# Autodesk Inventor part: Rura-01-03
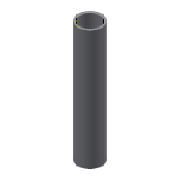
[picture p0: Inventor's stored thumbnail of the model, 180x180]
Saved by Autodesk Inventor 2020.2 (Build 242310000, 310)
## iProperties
Manager: www.cadconsulting.pl
Company: Fabian Stasiak CAD Consulting
IsCustomPart: 0
Created: 2014-07
Part Number: Rura-01-03
Material: Ogólny
Document SubType Name: Modeling
Designer: F.Stasiak
Language: pl-PL
Size Designation: 80
Categories: <MemberInstance><Categories><Category DisplayName="Rury cienko- i grubościenne" InternalName="4347fa0f-2144-441d-94cd-e3e15c92b736" Mnemonic="TUBEANDPIPE"><Cate
Density: 1 g/cm^3
Appearance: Domyślna
Catalog Web Link: www.expertbooks.pl
Author: F.Stasiak
Subject: Zbiór ćwiczeń. Autodesk Inventor 2020. Kurs Professional
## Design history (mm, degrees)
sketch "Szkic1"
  geometry: C1 r 40 at (0, 0); C2 r 45 at (0, 0); 1 further point
  constraints: 2 centre point, 2 coincident
  dimensions: "d0" = 80 diameter of C1 (= ID); "d1" = 90 diameter of C2 (= OD)
extrude "Wyciągnięcie proste1" new body sketch "Szkic1" distance "d2" = 250 (= L); taper "d3" = 0 deg
node "Punkt konstrukcyjny3"
node "Punkt konstrukcyjny4"
node "Oś konstrukcyjna3"
node "Oś konstrukcyjna4"
node "Bryła1"
other parameters: "L" = 250 [user parameter; used in 1 equation term], "ID" = 80 [user parameter; used in 1 equation term], "OD" = 90 [user parameter; used in 1 equation term]
